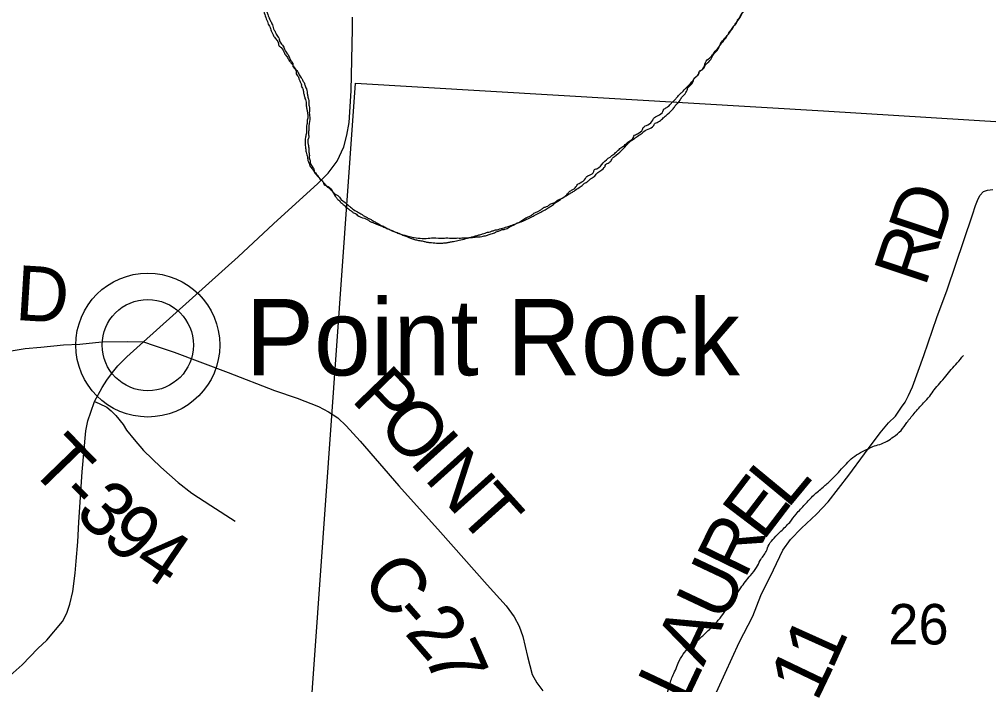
# Model space of a CAD drawing. Extents: x -13.7 to 34, y 0 to 32.3.
# Drawn here: x 26.441 to 27.443, y 16.374 to 17.062 of the extents above; entities that cross this region are included whole.
import ezdxf

# ---------------------------------------------------------------- set-up
doc = ezdxf.new("R2010")
doc.units = 0
for name, color, linetype in [('GM_X_Corporation', 7, 'Continuous'), ('GM_X_County_Road', 7, 'Continuous'), ('GM_X_County_Road_Text', 7, 'Continuous'), ('GM_X_Minor_River', 7, 'Continuous'), ('GM_X_Section_Text', 7, 'Continuous'), ('GM_X_State_Route', 7, 'Continuous'), ('GM_X_Township_Road', 7, 'Continuous'), ('GM_X_Township_Road_Text', 7, 'Continuous'), ('GM_X_Unincorporated', 7, 'Continuous'), ('GM_X_Unincorporated_Location', 7, 'Continuous'), ('GM_X_Unincorporated_Text', 7, 'Continuous')]:
    doc.layers.add(name, color=color, linetype=linetype)

msp = doc.modelspace()

# ---------------------------------------------------------------- linework, layer by layer
at = {"layer": 'GM_X_Corporation'}
msp.add_lwpolyline([(27.2726, 16.9674), (27.7957, 16.9352), (27.7886, 16.8172), (27.7611, 16.3953), (27.73, 15.9158), (26.7165, 15.9781), (26.789, 16.9963)], close=True, dxfattribs=at)
at = {"layer": 'GM_X_County_Road'}
msp.add_lwpolyline([(26.5697, 16.7286), (26.5808, 16.7248), (26.6016, 16.7179), (26.6573, 16.6968), (26.7051, 16.6785), (26.7285, 16.6704), (26.7505, 16.6617), (26.7609, 16.6563), (26.7705, 16.6501), (26.7794, 16.6418), (26.7939, 16.6261), (26.8338, 16.5798), (26.8769, 16.532), (26.9249, 16.4775), (26.9447, 16.4557), (26.9528, 16.4442), (26.9581, 16.4346), (26.962, 16.4241), (26.9667, 16.4033), (26.9715, 16.3845), (26.9762, 16.376), (26.9826, 16.3677)], dxfattribs=at)
at = {"layer": 'GM_X_Minor_River'}
for points in [[(26.6094, 17.3433), (26.612, 17.341), (26.6148, 17.3359), (26.6155, 17.3344), (26.6177, 17.332), (26.6203, 17.3281), (26.622, 17.3243), (26.625, 17.3211), (26.6275, 17.3173), (26.6282, 17.3153), (26.6304, 17.313), (26.6329, 17.3091), (26.6332, 17.3076), (26.6351, 17.3056), (26.6369, 17.3025), (26.6391, 17.2998), (26.6416, 17.2955), (26.6419, 17.294), (26.6437, 17.2916), (26.6462, 17.2874), (26.6466, 17.2859), (26.6495, 17.2812), (26.6509, 17.2781), (26.6516, 17.2762), (26.6526, 17.2735), (26.6544, 17.27), (26.6554, 17.2669), (26.6565, 17.2642), (26.6572, 17.2616), (26.6575, 17.26), (26.6582, 17.2577), (26.6595, 17.2535), (26.6602, 17.2512), (26.6605, 17.2493), (26.6615, 17.2447), (26.6622, 17.2428), (26.6629, 17.2393), (26.6639, 17.2359), (26.6645, 17.2324), (26.6645, 17.2309), (26.6655, 17.2282), (26.6668, 17.2213), (26.6671, 17.2191), (26.6678, 17.2168), (26.6681, 17.2141), (26.6684, 17.2122), (26.6687, 17.2091), (26.669, 17.2061), (26.6689, 17.2046), (26.6693, 17.203), (26.6696, 17.2007), (26.6695, 17.1981), (26.6698, 17.1958), (26.6694, 17.1829), (26.6696, 17.1802), (26.6696, 17.1779), (26.6699, 17.176), (26.6702, 17.1737), (26.6698, 17.1605), (26.67, 17.157), (26.6699, 17.154), (26.6702, 17.1517), (26.6708, 17.1464), (26.6711, 17.1441), (26.6718, 17.1418), (26.6721, 17.1395), (26.6728, 17.1368), (26.6741, 17.1307), (26.6747, 17.1272), (26.6758, 17.1242), (26.6765, 17.1226), (26.6771, 17.1192), (26.6785, 17.1157), (26.6785, 17.1142), (26.6795, 17.1119), (26.6806, 17.1092), (26.6816, 17.1061), (26.683, 17.1026), (26.683, 17.1007), (26.6844, 17.0984), (26.6858, 17.0949), (26.6861, 17.093), (26.6865, 17.0915), (26.6879, 17.0888), (26.6896, 17.0838), (26.6895, 17.0819), (26.691, 17.0796), (26.692, 17.0761), (26.6923, 17.0746), (26.6931, 17.073), (26.6941, 17.0704), (26.6962, 17.0642), (26.6972, 17.0615), (26.6979, 17.06), (26.6986, 17.0573), (26.7, 17.055), (26.7011, 17.0526)], [(26.6657, 17.2225), (26.6664, 17.2183), (26.6666, 17.2138), (26.6679, 17.2076), (26.6678, 17.2057), (26.6685, 17.2015), (26.6688, 17.2), (26.6694, 17.1958), (26.6697, 17.1943), (26.6704, 17.1901), (26.6703, 17.1882), (26.6706, 17.1851), (26.6712, 17.1805), (26.6711, 17.179), (26.6718, 17.1763), (26.6724, 17.1725), (26.6723, 17.1691), (26.6729, 17.1649), (26.6729, 17.1634), (26.6735, 17.1599), (26.6734, 17.1573), (26.6744, 17.1527), (26.6746, 17.147), (26.6753, 17.1451), (26.676, 17.142), (26.6769, 17.137), (26.6773, 17.1351), (26.6779, 17.1324), (26.6786, 17.129), (26.6806, 17.1213), (26.6809, 17.1198), (26.6819, 17.1156), (26.6823, 17.1141), (26.6833, 17.1117), (26.6844, 17.1087), (26.685, 17.106), (26.6857, 17.1029), (26.6856, 17.1014), (26.6867, 17.0991), (26.6881, 17.0945), (26.6884, 17.0926), (26.6898, 17.0891), (26.6911, 17.0841), (26.6914, 17.0818), (26.6932, 17.0787), (26.695, 17.0745), (26.6953, 17.073), (26.6968, 17.0706), (26.6982, 17.0672), (26.6992, 17.0645), (26.7006, 17.0614), (26.7017, 17.0595), (26.7024, 17.0575), (26.7035, 17.0552), (26.7041, 17.0525), (26.7059, 17.0494), (26.707, 17.0467), (26.7095, 17.0429), (26.7109, 17.0386), (26.7142, 17.0343), (26.7159, 17.0305), (26.7188, 17.0262), (26.7206, 17.0224), (26.7224, 17.0193), (26.7242, 17.0158), (26.7241, 17.0143), (26.7259, 17.0115), (26.7277, 17.0073), (26.7276, 17.0058), (26.7291, 17.0038), (26.7305, 17.0007), (26.7316, 16.9977), (26.733, 16.9946), (26.7329, 16.9931), (26.734, 16.9911), (26.735, 16.9877), (26.7357, 16.9842), (26.7367, 16.9804), (26.738, 16.9754), (26.738, 16.9739), (26.7386, 16.9697), (26.7392, 16.9663), (26.7395, 16.9636), (26.7394, 16.959), (26.7389, 16.9568), (26.7389, 16.9545), (26.7384, 16.9522), (26.7381, 16.9446), (26.7377, 16.9424), (26.7373, 16.9405), (26.737, 16.9318), (26.7373, 16.9291), (26.7379, 16.9249), (26.7392, 16.9195), (26.7395, 16.9176), (26.7402, 16.9149), (26.7413, 16.9126)], [(27.0468, 16.9101), (27.0476, 16.912), (27.0511, 16.9141), (27.0538, 16.9171), (27.0546, 16.9186), (27.0566, 16.9204), (27.0703, 16.9333), (27.0727, 16.9358), (27.0742, 16.9369), (27.0781, 16.9395), (27.0824, 16.9427), (27.0843, 16.9438), (27.0859, 16.9453), (27.0913, 16.9485), (27.0971, 16.9525), (27.0979, 16.954), (27.1018, 16.9561), (27.1061, 16.9594), (27.11, 16.9627), (27.1159, 16.9682), (27.1186, 16.9715), (27.1195, 16.973), (27.1218, 16.9752), (27.125, 16.9797), (27.1258, 16.9812), (27.1286, 16.9841), (27.1317, 16.989), (27.1322, 16.9909), (27.1349, 16.9938), (27.1381, 16.9986), (27.1386, 17.0005), (27.1409, 17.0027), (27.1437, 17.0064), (27.1441, 17.0079), (27.1469, 17.0101), (27.1497, 17.0142), (27.1501, 17.0161), (27.1537, 17.0213), (27.1557, 17.0231), (27.1584, 17.0261), (27.1616, 17.0302), (27.1643, 17.0335), (27.1667, 17.0368), (27.1695, 17.0402), (27.1719, 17.0431), (27.1735, 17.0457), (27.1747, 17.0476), (27.1751, 17.0491), (27.1771, 17.0509), (27.1795, 17.0543), (27.1815, 17.0572), (27.1842, 17.0609), (27.1883, 17.0677), (27.1891, 17.0691), (27.193, 17.0747), (27.1931, 17.0762), (27.1951, 17.0781), (27.1963, 17.0803), (27.1983, 17.0837), (27.2007, 17.0885), (27.2012, 17.0908), (27.2036, 17.0945), (27.2064, 17.1001), (27.2073, 17.1027), (27.2096, 17.1061), (27.2125, 17.1113), (27.2129, 17.1128), (27.2146, 17.1166), (27.2154, 17.1181), (27.217, 17.1207), (27.2186, 17.1244), (27.2202, 17.1278), (27.2219, 17.1319), (27.2223, 17.1334), (27.2243, 17.1356), (27.2263, 17.1393), (27.2267, 17.1409), (27.2295, 17.1453), (27.2308, 17.1479), (27.2312, 17.1498), (27.2336, 17.1532), (27.234, 17.1547), (27.2356, 17.1569), (27.2385, 17.1621), (27.2389, 17.1636), (27.2413, 17.1666), (27.244, 17.1703), (27.2441, 17.1722), (27.2465, 17.1748), (27.2485, 17.1785), (27.2489, 17.18), (27.2505, 17.1822), (27.2525, 17.1864), (27.2546, 17.1901), (27.2566, 17.1946), (27.2571, 17.1965), (27.2586, 17.1987)], [(26.913, 16.8382), (26.9165, 16.8392), (26.9203, 16.8402), (26.923, 16.8412), (26.928, 16.8426), (26.9311, 16.8436), (26.9364, 16.845), (26.9425, 16.8467), (26.9479, 16.8484), (26.9537, 16.8505), (26.9571, 16.8519), (26.9602, 16.8529), (26.9633, 16.8543), (26.9683, 16.8565), (26.9791, 16.8622), (26.9841, 16.8647), (26.988, 16.8672), (26.9915, 16.8694), (26.9954, 16.8723), (26.9997, 16.8752), (27.0043, 16.8784), (27.0082, 16.8817), (27.0091, 16.8832), (27.0122, 16.8854), (27.0168, 16.889), (27.0176, 16.8905), (27.0211, 16.8931), (27.0266, 16.8975), (27.0274, 16.899), (27.0309, 16.9011), (27.0352, 16.9048), (27.0356, 16.9063), (27.0383, 16.9077), (27.045, 16.9139), (27.052, 16.9198), (27.0559, 16.9227), (27.0594, 16.926), (27.0633, 16.9293), (27.0668, 16.9318), (27.0704, 16.9351), (27.0723, 16.9366), (27.0762, 16.9399), (27.0766, 16.9414), (27.0805, 16.9439), (27.0856, 16.9483), (27.0864, 16.9502), (27.0911, 16.9531), (27.0962, 16.9579), (27.097, 16.9597), (27.1016, 16.9626), (27.1067, 16.967), (27.1075, 16.9689), (27.1107, 16.9711), (27.1138, 16.9736), (27.1154, 16.9755), (27.1181, 16.978), (27.1205, 16.9806), (27.122, 16.9825), (27.1248, 16.9854), (27.1275, 16.988), (27.1323, 16.9931), (27.1378, 16.999), (27.1405, 17.0024), (27.1441, 17.0064), (27.1445, 17.0079), (27.1473, 17.0101), (27.15, 17.0138), (27.1508, 17.0153), (27.154, 17.0183), (27.1576, 17.0235), (27.1588, 17.0257), (27.1639, 17.0316), (27.1647, 17.0339), (27.1684, 17.0398), (27.1731, 17.0454), (27.1775, 17.0517), (27.1783, 17.0535), (27.1807, 17.0561), (27.1835, 17.0602), (27.1839, 17.0617), (27.1859, 17.0639), (27.1879, 17.0677), (27.1899, 17.0706), (27.1919, 17.0747), (27.1923, 17.0763), (27.1939, 17.0785), (27.196, 17.0822), (27.1964, 17.0841), (27.1984, 17.0871), (27.2008, 17.0923), (27.2013, 17.0942), (27.2041, 17.0983), (27.2073, 17.1046), (27.2078, 17.1077), (27.2106, 17.1121), (27.2139, 17.1185), (27.2143, 17.1211)], [(26.7011, 17.0526), (26.7018, 17.0503), (26.7032, 17.0476), (26.7046, 17.0445), (26.7072, 17.041), (26.7093, 17.0372), (26.7096, 17.0353), (26.7122, 17.0329), (26.7154, 17.0271), (26.7165, 17.0255), (26.718, 17.0236), (26.7191, 17.0216), (26.7201, 17.0201), (26.7216, 17.0178), (26.7238, 17.0154), (26.7256, 17.0127), (26.7274, 17.0104), (26.7303, 17.0057), (26.7314, 17.0038), (26.7328, 17.0018), (26.7339, 17.0003), (26.7346, 16.9987), (26.7361, 16.996), (26.7364, 16.9945), (26.7381, 16.9902), (26.7388, 16.9872), (26.7394, 16.9837), (26.7398, 16.9818), (26.7404, 16.9795), (26.7407, 16.975), (26.7406, 16.9734), (26.7413, 16.9711), (26.7411, 16.9654), (26.7414, 16.9628), (26.7411, 16.9544), (26.7406, 16.951), (26.7406, 16.9487), (26.7405, 16.9472), (26.7404, 16.9427), (26.7407, 16.9408), (26.7402, 16.9393), (26.74, 16.9328), (26.7406, 16.9282), (26.7406, 16.9259), (26.7412, 16.9214), (26.7411, 16.9191), (26.7418, 16.9168), (26.7421, 16.9153), (26.7424, 16.9133), (26.7449, 16.9091), (26.746, 16.9071), (26.7463, 16.9049), (26.7507, 16.899), (26.7518, 16.8975), (26.7558, 16.8931), (26.7561, 16.8916), (26.7591, 16.89), (26.7679, 16.8794), (26.7701, 16.8767), (26.773, 16.8736), (26.7748, 16.872), (26.7778, 16.8692), (26.7815, 16.8661), (26.783, 16.8649), (26.7844, 16.8641), (26.787, 16.8621), (26.7889, 16.8613), (26.7908, 16.8597), (26.7982, 16.8564), (26.8009, 16.8552), (26.8035, 16.8536), (26.8061, 16.8523), (26.8091, 16.8511), (26.8124, 16.8498), (26.8162, 16.8482), (26.8203, 16.8465), (26.8248, 16.8445), (26.8285, 16.8428), (26.833, 16.8412), (26.8357, 16.84), (26.8379, 16.8391), (26.842, 16.8375), (26.8499, 16.8345), (26.854, 16.8336), (26.859, 16.8327), (26.8623, 16.8319), (26.8657, 16.8314), (26.8726, 16.8308), (26.8779, 16.8306), (26.8802, 16.8309), (26.8828, 16.8312), (26.8863, 16.8318), (26.8901, 16.8325), (26.8962, 16.8338), (26.9031, 16.8354), (26.9092, 16.8371), (26.913, 16.8382)], [(26.7413, 16.9126), (26.7416, 16.9111), (26.743, 16.9088), (26.7445, 16.9072), (26.746, 16.9052), (26.7489, 16.9017), (26.7507, 16.8994), (26.7529, 16.8967), (26.7543, 16.8951), (26.7573, 16.8919), (26.7591, 16.8896), (26.7635, 16.886), (26.7668, 16.8825), (26.7717, 16.8789), (26.7731, 16.8774), (26.7746, 16.8754), (26.7768, 16.8738), (26.7823, 16.8691), (26.7838, 16.8679), (26.7857, 16.8663), (26.7909, 16.8631), (26.7957, 16.8603), (26.8009, 16.8571), (26.8043, 16.8554), (26.8073, 16.8538), (26.8091, 16.8526), (26.811, 16.8518), (26.8132, 16.8502), (26.8155, 16.849), (26.8177, 16.8482), (26.8214, 16.8461), (26.8259, 16.8441), (26.8289, 16.8428), (26.8315, 16.8416), (26.8338, 16.8408), (26.8421, 16.8382), (26.8473, 16.8369), (26.8496, 16.8365), (26.8659, 16.8359), (26.8693, 16.8362), (26.8799, 16.8358), (26.8822, 16.8361), (26.8845, 16.8361), (26.8879, 16.8359), (26.8917, 16.8358), (26.8947, 16.8361), (26.8974, 16.836), (26.9001, 16.8363), (26.9046, 16.8361), (26.9065, 16.8365), (26.91, 16.8367), (26.9126, 16.837), (26.9157, 16.8373), (26.9179, 16.8372), (26.921, 16.8379), (26.9252, 16.8389), (26.9291, 16.8403), (26.9317, 16.8409), (26.9337, 16.842), (26.9352, 16.8427), (26.9383, 16.8438), (26.9398, 16.8445), (26.9433, 16.8451), (26.9479, 16.8473), (26.9579, 16.8522), (26.9618, 16.8548), (26.9641, 16.8562), (26.9661, 16.8573), (26.9684, 16.8584), (26.9711, 16.8598), (26.9734, 16.8616), (26.975, 16.8623), (26.978, 16.8637), (26.9804, 16.8652), (26.9831, 16.8674), (26.985, 16.8681), (26.9877, 16.8691), (26.99, 16.8709), (26.992, 16.8716), (26.9958, 16.8734), (26.9993, 16.8759), (27.0012, 16.8766), (27.0059, 16.8792), (27.0078, 16.8802), (27.0098, 16.8817), (27.0132, 16.8835), (27.0148, 16.8846), (27.0202, 16.8882), (27.0222, 16.8896), (27.0257, 16.8926), (27.0292, 16.8947), (27.0319, 16.8973), (27.0338, 16.8984), (27.037, 16.9009), (27.0386, 16.9031), (27.0424, 16.9057), (27.0468, 16.9101)], [(27.0994, 16.2682), (27.1009, 16.2756), (27.1022, 16.2908), (27.1029, 16.2999), (27.1031, 16.3082), (27.1038, 16.3162), (27.1044, 16.3226), (27.1054, 16.3302), (27.1065, 16.3404), (27.1083, 16.3506), (27.1128, 16.371), (27.1166, 16.3826), (27.1195, 16.389), (27.1224, 16.3965), (27.1276, 16.4055), (27.134, 16.4132), (27.1406, 16.4183), (27.1488, 16.4257), (27.1582, 16.4345), (27.1657, 16.443), (27.1713, 16.4508), (27.1753, 16.4575), (27.1816, 16.466), (27.1872, 16.4742), (27.192, 16.4808), (27.1971, 16.4871), (27.2035, 16.4953), (27.2071, 16.5024), (27.2135, 16.512), (27.2164, 16.5192), (27.2216, 16.5258), (27.2286, 16.5328), (27.2377, 16.542), (27.2444, 16.5505), (27.2535, 16.5605), (27.2625, 16.5701), (27.2723, 16.5785), (27.2805, 16.5858), (27.288, 16.5936), (27.2947, 16.6009), (27.3013, 16.6076), (27.3087, 16.613), (27.3172, 16.6173), (27.3238, 16.6205), (27.3307, 16.6225), (27.3384, 16.6261), (27.345, 16.6304), (27.3528, 16.637), (27.3588, 16.6452), (27.3663, 16.6544), (27.3761, 16.6655), (27.3824, 16.6725), (27.3872, 16.6792), (27.3928, 16.6858), (27.3991, 16.6932), (27.4046, 16.6999), (27.4109, 16.7069), (27.4172, 16.7147)]]:
    msp.add_spline(points, degree=3, dxfattribs=at)
at = {"layer": 'GM_X_State_Route'}
msp.add_lwpolyline([(26.4321, 16.3836), (26.4443, 16.3948), (26.4606, 16.4116), (26.4697, 16.4203), (26.4859, 16.4396), (26.4904, 16.4481), (26.4936, 16.4573), (26.4967, 16.4705), (26.4993, 16.4895), (26.5003, 16.5017), (26.5018, 16.522), (26.5028, 16.5423), (26.5064, 16.5944), (26.5101, 16.6367), (26.5121, 16.647), (26.5153, 16.6561), (26.519, 16.6671), (26.5269, 16.6813), (26.532, 16.6892), (26.5377, 16.6971), (26.5432, 16.7038), (26.5525, 16.713), (26.5697, 16.7286), (26.6675, 16.8167), (26.704, 16.8506), (26.7498, 16.8923), (26.7607, 16.9032), (26.7698, 16.9154), (26.7769, 16.9305), (26.7799, 16.9424), (26.7824, 16.9554), (26.7844, 16.9883), (26.7858, 17.0525), (26.7859, 17.0644)], dxfattribs=at)
at = {"layer": 'GM_X_Township_Road'}
for points in [[(27.1492, 16.3386), (27.1854, 16.4178), (27.1997, 16.445), (27.2078, 16.4662), (27.221, 16.493), (27.2306, 16.5131), (27.2385, 16.5243), (27.2498, 16.5361), (27.2654, 16.5504), (27.2775, 16.5632), (27.2987, 16.5907), (27.315, 16.613), (27.3312, 16.6346), (27.3398, 16.6448), (27.3472, 16.6519), (27.3533, 16.661), (27.3571, 16.6663), (27.3606, 16.6732), (27.3645, 16.6823), (27.3765, 16.7146), (27.3897, 16.7538), (27.4003, 16.7825), (27.4268, 16.8599), (27.4299, 16.8696), (27.4319, 16.8749), (27.4342, 16.8799), (27.4381, 16.884), (27.4422, 16.8856), (27.4477, 16.8862)], [(26.4174, 16.72), (26.4183, 16.7197), (26.4247, 16.7184), (26.43, 16.7186), (26.4349, 16.7196), (26.4473, 16.7218), (26.4637, 16.7233), (26.4872, 16.7254), (26.504, 16.7263), (26.5266, 16.7286), (26.5528, 16.729), (26.5697, 16.7286)], [(26.519, 16.6671), (26.5239, 16.6649), (26.5318, 16.661), (26.5365, 16.6572), (26.5413, 16.6525), (26.5486, 16.6431), (26.5523, 16.6373), (26.5602, 16.6275), (26.5697, 16.6162), (26.5878, 16.5989), (26.6056, 16.5831), (26.6197, 16.5723), (26.6395, 16.5593), (26.6645, 16.5431)]]:
    msp.add_lwpolyline(points, dxfattribs=at)
at = {"layer": 'GM_X_Unincorporated'}
for radius in [0.0744, 0.0472]:
    msp.add_circle((26.5742, 16.7253), radius, dxfattribs=at)
at = {"layer": 'GM_X_Unincorporated_Location'}
msp.add_line((26.5742, 16.7253), (26.5742, 16.7253), dxfattribs=at)

# ---------------------------------------------------------------- texts
at = {"layer": 'GM_X_County_Road_Text'}
for s, rotation, p in [('P', 314.1466, (26.7834, 16.6685)), ('O', 312.1074, (26.8098, 16.6414)), ('I', 311.9988, (26.8433, 16.6043)), ('N', 312.0054, (26.8589, 16.587)), ('T', 312.0031, (26.8924, 16.5498)), ('C', 310.991, (26.7927, 16.4801)), ('-', 310.9869, (26.8233, 16.4449)), ('2', 310.901, (26.8386, 16.4273)), ('7', 293.6035, (26.8591, 16.4046))]:
    msp.add_text(s, height=0.0568, rotation=rotation, dxfattribs=at).set_placement(p)
at = {"layer": 'GM_X_Section_Text'}
msp.add_text('26', height=0.04186, rotation=0, dxfattribs=at).set_placement((27.3397, 16.4157))
at = {"layer": 'GM_X_Township_Road_Text'}
for s, rotation, p in [('D', 71.3531, (27.3924, 16.8286)), ('R', 71.5626, (27.3776, 16.7844)), ('D', 356.404, (26.4363, 16.7514)), ('T', 314.1, (26.4497, 16.5988)), ('L', 50.3793, (27.2354, 16.5549)), ('E', 52.7144, (27.21, 16.5215)), ('-', 314.6019, (26.4796, 16.5679)), ('3', 316.1835, (26.4972, 16.55)), ('9', 318.8182, (26.5246, 16.5239)), ('R', 63.9813, (27.1911, 16.4821)), ('4', 325.7973, (26.5569, 16.4962)), ('U', 64.6781, (27.1698, 16.4371)), ('A', 64.6816, (27.1484, 16.3919)), ('1', 65.762, (27.2814, 16.3882)), ('1', 64.4239, (27.2657, 16.3553)), ('L', 64.6808, (27.1302, 16.3535))]:
    msp.add_text(s, height=0.0568, rotation=rotation, dxfattribs=at).set_placement(p)
at = {"layer": 'GM_X_Unincorporated_Text'}
msp.add_text('Point Rock', height=0.07898, rotation=0, dxfattribs=at).set_placement((26.6755, 16.694))

doc.saveas('drawing.dxf')
